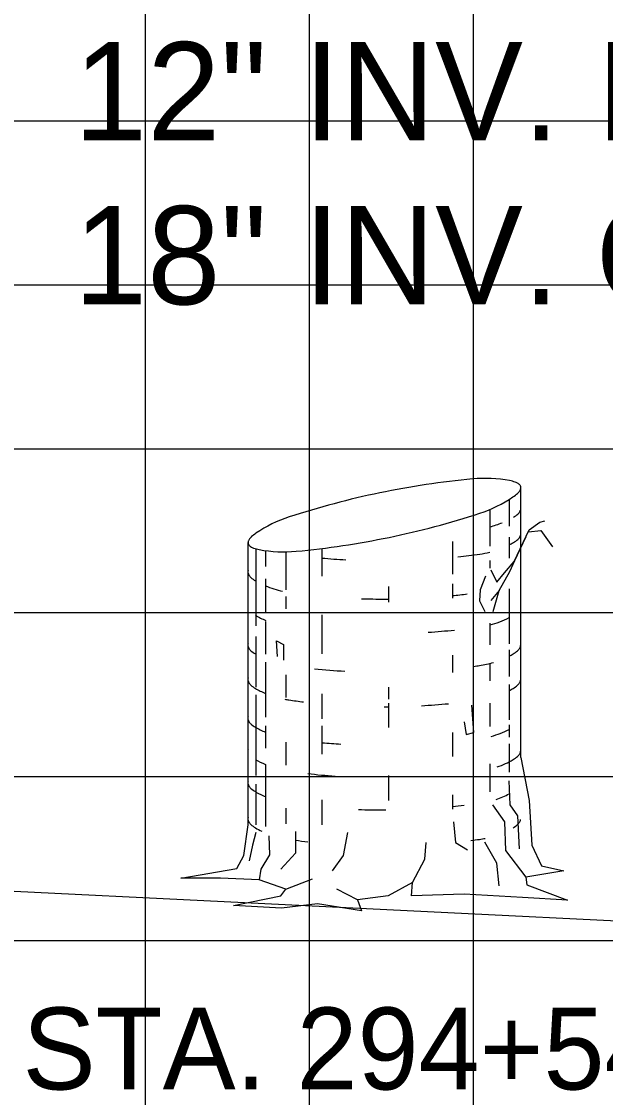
# Model space of a CAD drawing. Extents: x 859352 to 859522, y 366268 to 366378.
# Drawn here: x 859467.37 to 859470.94, y 366286.28 to 366292.84 of the extents above; entities that cross this region are included whole.
import ezdxf

# ---------------------------------------------------------------- set-up
doc = ezdxf.new("R2010")
doc.units = 0
for name, color, linetype in [('D_Drainage_Text', 7, 'Continuous'), ('D_Text_Monospaced', 7, 'Continuous'), ('MAJOR', 7, 'Continuous'), ('MINOR', 7, 'Continuous'), ('S_Roadway_Centerline', 7, 'Continuous'), ('S_Trees_Conifer_Pay', 7, 'Continuous')]:
    doc.layers.add(name, color=color, linetype=linetype)

msp = doc.modelspace()

# ---------------------------------------------------------------- linework, layer by layer
at = {"layer": 'MAJOR'}
for p, q in [((859470.1294, 366277.2365), (859470.1294, 366297.2365)), ((859365.1294, 366292.2365), (859505.1294, 366292.2365)), ((859365.1294, 366287.2365), (859505.1294, 366287.2365))]:
    msp.add_line(p, q, dxfattribs=at)
at = {"layer": 'MINOR'}
for p, q in [((859468.1294, 366277.2365), (859468.1294, 366297.2365)), ((859469.1294, 366277.2365), (859469.1294, 366297.2365)), ((859365.1294, 366291.2365), (859505.1294, 366291.2365)), ((859365.1294, 366290.2365), (859505.1294, 366290.2365)), ((859365.1294, 366289.2365), (859505.1294, 366289.2365)), ((859365.1294, 366288.2365), (859505.1294, 366288.2365))]:
    msp.add_line(p, q, dxfattribs=at)
at = {"layer": 'S_Roadway_Centerline'}
msp.add_lwpolyline([(859463.9377, 366287.7043), (859477.1652, 366287.052), (859487.7669, 366286.7914)], dxfattribs=at)
at = {"layer": 'S_Trees_Conifer_Pay'}
for p, q in [((859470.4189, 366288.352), (859470.4189, 366289.999)), ((859470.3474, 366289.9268), (859470.3474, 366289.7641)), ((859470.2299, 366289.8658), (859470.2299, 366289.6427)), ((859468.7549, 366287.9419), (859468.7549, 366289.6637)), ((859470.0016, 366289.6696), (859470.0016, 366289.4701)), ((859470.3474, 366289.6965), (859470.3474, 366289.5685)), ((859468.8021, 366289.6263), (859468.8021, 366289.1551)), ((859468.8605, 366289.6151), (859468.8605, 366289.5173)), ((859468.9858, 366289.6072), (859468.9858, 366289.375)), ((859469.2056, 366289.6276), (859469.2056, 366289.4596)), ((859470.2299, 366289.5541), (859470.2299, 366289.5068)), ((859468.8605, 366289.4432), (859468.8605, 366289.2391)), ((859469.6112, 366289.396), (859469.6112, 366289.3008)), ((859470.0016, 366289.4124), (859470.0016, 366289.3238)), ((859468.9858, 366289.3343), (859468.9858, 366289.2601)), ((859470.287, 366289.371), (859470.2358, 366289.3113)), ((859470.3474, 366289.3815), (859470.3474, 366289.0456)), ((859469.2056, 366289.2227), (859469.2056, 366288.9859)), ((859468.8605, 366289.1814), (859468.8605, 366288.9819)), ((859470.2299, 366289.1715), (859470.2299, 366289.0397)), ((859468.8021, 366289.0908), (859468.8021, 366288.7824)), ((859470.3474, 366289.0088), (859470.3474, 366288.8461)), ((859468.8605, 366288.9347), (859468.8605, 366288.5987)), ((859470.0016, 366288.976), (859470.0016, 366288.871)), ((859470.2299, 366288.9288), (859470.2299, 366288.8192)), ((859468.9858, 366288.8566), (859468.9858, 366288.7181)), ((859470.3474, 366288.7988), (859470.3474, 366288.5823)), ((859468.8021, 366288.7352), (859468.8021, 366288.2431)), ((859469.2056, 366288.7411), (859469.2056, 366288.5889)), ((859469.6112, 366288.7824), (859469.6112, 366288.7083)), ((859469.6112, 366288.6834), (859469.6112, 366288.5351)), ((859470.2299, 366288.6834), (859470.2299, 366288.5416)), ((859468.8605, 366288.5456), (859468.8605, 366288.4097)), ((859469.2056, 366288.5456), (859469.2056, 366288.3723)), ((859470.3474, 366288.5515), (859470.3474, 366288.4773)), ((859470.0016, 366288.5042), (859470.0016, 366288.3579)), ((859468.9858, 366288.4465), (859468.9858, 366288.3048)), ((859470.3474, 366288.4366), (859470.3474, 366288.2634)), ((859468.8605, 366288.3107), (859468.8605, 366287.932)), ((859470.2299, 366288.3146), (859470.2299, 366288.142)), ((859469.6112, 366288.2431), (859469.6112, 366288.0902)), ((859468.8021, 366288.1893), (859468.8021, 366287.9419)), ((859469.2056, 366288.0948), (859469.2056, 366287.9419)), ((859470.0016, 366288.1256), (859470.0016, 366288.037)), ((859468.9858, 366288.0429), (859468.9858, 366287.9485)), ((859468.9858, 366287.5488), (859469.1486, 366287.6125)), ((859469.4228, 366287.4845), (859469.2969, 366287.5488))]:
    msp.add_line(p, q, dxfattribs=at)
for points in [[(859470.2358, 366289.497), (859470.2726, 366289.4229), (859470.3198, 366289.4799), (859470.3776, 366289.5482), (859470.4701, 366289.7418), (859470.5344, 366289.789), (859470.5652, 366289.7956)], [(859470.4648, 366289.7299), (859470.5403, 366289.7378), (859470.6125, 366289.6387)], [(859470.2503, 366289.2437), (859470.287, 366289.371), (859470.3507, 366289.4865), (859470.3815, 366289.5541), (859470.4504, 366289.7004)], [(859470.2024, 366289.4596), (859470.1715, 366289.375), (859470.1676, 366289.3074), (859470.1984, 366289.2437)], [(859468.934, 366288.9694), (859468.9281, 366289.0646), (859468.9714, 366289.0416), (859468.9714, 366288.9471)], [(859470.0731, 366288.5705), (859470.0856, 366288.4937), (859470.1328, 366288.5042), (859470.1203, 366288.6709)], [(859470.4189, 366288.352), (859470.4701, 366288.0902), (859470.4865, 366287.8166), (859470.5442, 366287.6912), (859470.6801, 366287.6604), (859470.4497, 366287.623), (859470.4497, 366287.623), (859470.4556, 366287.5758), (859470.703, 366287.4813), (859470.4287, 366287.4977), (859470.0731, 366287.518), (859469.7516, 366287.5075), (859469.7581, 366287.5902), (859469.6098, 366287.5075), (859469.4228, 366287.4845), (859469.4471, 366287.417), (859469.1794, 366287.4603), (859468.9589, 366287.4334), (859468.6663, 366287.4504), (859468.955, 366287.5075), (859468.9858, 366287.5488), (859468.8231, 366287.6066), (859468.5862, 366287.6171), (859468.3454, 366287.6171), (859468.6873, 366287.6748), (859468.7286, 366287.7549), (859468.7549, 366287.9419)], [(859470.3448, 366288.2096), (859470.3507, 366288.0639), (859470.3979, 366287.9957), (859470.4084, 366287.7962)], [(859470.2457, 366288.0639), (859470.3198, 366287.959), (859470.3244, 366287.7857), (859470.4497, 366287.623)], [(859470.0088, 366287.959), (859470.0193, 366287.833), (859470.0934, 366287.7897)], [(859468.8028, 366287.8946), (859468.7818, 366287.8166), (859468.7614, 366287.7221)], [(859468.8808, 366287.8743), (859468.8868, 366287.7588), (859468.8336, 366287.6702), (859468.8231, 366287.6066)], [(859469.0436, 366287.9012), (859469.0436, 366287.7693), (859468.955, 366287.6702)], [(859469.27, 366287.6604), (859469.3375, 366287.7549), (859469.3644, 366287.8946)], [(859469.7581, 366287.5902), (859469.8323, 366287.7319), (859469.8421, 366287.833)], [(859470.287, 366287.5698), (859470.2726, 366287.7076), (859470.1984, 366287.8369)]]:
    msp.add_lwpolyline(points, dxfattribs=at)
for centre, radius, start, end in [((859470.6107, 366284.8962), 5.1788, 95.37941, 101.7194), ((859470.2004, 366289.2541), 0.8016, 79.2194, 95.37941), ((859470.3034, 366289.7953), 0.2506, 71.05013, 79.2194), ((859470.3583, 366289.9551), 0.0817, 56.7194, 71.05013), ((859470.3439, 366290.0245), 0.0817, 312.38868, 326.7194), ((859470.3742, 366289.9793), 0.0527, 46.92298, 56.7194), ((859470.3887, 366289.9949), 0.0314, 34.2194, 46.92298), ((859470.3681, 366290.0086), 0.0527, 326.7194, 336.51582), ((859470.3929, 366289.9977), 0.0264, 23.40735, 34.2194), ((859470.3877, 366290.0001), 0.0314, 336.51582, 349.2194), ((859470.3963, 366289.9992), 0.0226, 11.7194, 23.40735), ((859470.3963, 366289.9992), 0.0226, 0.03145, 11.7194), ((859470.3925, 366289.9992), 0.0264, 349.2194, 0.03145), ((859470.6107, 366284.8962), 5.1788, 101.7194, 108.05939), ((859469.9202, 366290.6049), 0.8016, 288.05939, 304.2194), ((859470.23, 366290.1492), 0.2506, 304.2194, 312.38868), ((859470.3596, 366289.8848), 0.0624, 311.25059, 330), ((859470.3755, 366289.8757), 0.0441, 330, 343.94846), ((859470.3858, 366289.8727), 0.0334, 343.94846, 354.21506), ((859469.2538, 366289.0577), 0.8016, 108.05939, 124.2194), ((859468.5632, 366294.7664), 5.1788, 281.7194, 288.05939), ((859470.088, 366290.3125), 0.5707, 284.43166, 292.41325), ((859470.2872, 366289.9674), 0.1723, 300, 311.25059), ((859468.9439, 366289.5133), 0.2506, 124.2194, 132.38868), ((859470.3858, 366289.7183), 0.0334, 343.94846, 354.21506), ((859468.7814, 366289.6634), 0.0264, 169.2194, 180.03145), ((859468.7776, 366289.6634), 0.0226, 180.03145, 191.7194), ((859468.7863, 366289.6625), 0.0314, 156.51582, 169.2194), ((859468.7776, 366289.6634), 0.0226, 191.7194, 203.40735), ((859468.7811, 366289.6649), 0.0264, 203.40735, 214.2194), ((859468.8058, 366289.654), 0.0527, 146.7194, 156.51582), ((859468.7852, 366289.6677), 0.0314, 214.2194, 226.92298), ((859468.8301, 366289.638), 0.0817, 132.38868, 146.7194), ((859468.5632, 366294.7664), 5.1788, 275.37941, 281.7194), ((859470.088, 366290.1581), 0.5707, 297.0237, 300), ((859470.2872, 366289.813), 0.1723, 300, 311.25059), ((859470.3596, 366289.7304), 0.0624, 311.25059, 330), ((859470.3755, 366289.7213), 0.0441, 330, 343.94846), ((859468.7998, 366289.6833), 0.0527, 226.92298, 236.7194), ((859468.8157, 366289.7075), 0.0817, 236.7194, 251.05013), ((859468.8705, 366289.8672), 0.2506, 251.05013, 259.2194), ((859468.9736, 366290.4085), 0.8016, 259.2194, 275.37941), ((859469.5871, 366293.6756), 4.1237, 276.23804, 278.1032), ((859470.088, 366290.1581), 0.5707, 278.1032, 284.36665), ((859469.5871, 366293.6756), 4.1237, 264.6955, 266.73309), ((859468.787, 366289.4854), 0.0334, 163.94846, 180), ((859468.787, 366289.4854), 0.0334, 180, 196.05154), ((859468.7974, 366289.4884), 0.0441, 196.05154, 210), ((859468.8132, 366289.4975), 0.0624, 210, 228.74941), ((859468.8856, 366289.5801), 0.1723, 228.74941, 240), ((859469.0849, 366289.9252), 0.5707, 240, 240.33672), ((859469.0849, 366289.9252), 0.5707, 246.85973, 257.98457), ((859469.5857, 366293.4427), 4.1237, 268.07512, 270), ((859469.5857, 366293.4427), 4.1237, 270, 270.35814), ((859469.5857, 366293.4427), 4.1237, 275.78493, 277.05584), ((859470.3856, 366289.2743), 0.0334, 343.94846, 354.21506), ((859469.0862, 366289.7141), 0.5707, 240, 247.05866), ((859470.0878, 366289.7141), 0.5707, 284.44928, 297.04285), ((859469.587, 366293.2317), 4.1237, 273.70524, 275.95043), ((859468.787, 366289.0386), 0.0334, 163.94846, 180), ((859468.787, 366289.0386), 0.0334, 180, 196.05154), ((859468.7974, 366289.0416), 0.0441, 196.05154, 210), ((859468.8132, 366289.0507), 0.0624, 210, 228.74941), ((859468.8856, 366289.1333), 0.1723, 228.74941, 240), ((859470.2857, 366289.1333), 0.1723, 300, 311.25059), ((859470.3582, 366289.0507), 0.0624, 311.25059, 330), ((859470.374, 366289.0416), 0.0441, 330, 343.94846), ((859470.3843, 366289.0386), 0.0334, 343.94846, 354.21506), ((859469.0849, 366289.4784), 0.5707, 240, 240.33672), ((859470.0865, 366289.4784), 0.5707, 278.1032, 286.92962), ((859470.0865, 366289.4784), 0.5707, 297.18959, 300), ((859469.5857, 366292.9959), 4.1237, 264.08098, 266.66759), ((859469.5857, 366292.9959), 4.1237, 277.61247, 278.1032), ((859468.787, 366288.8286), 0.0334, 163.94846, 180), ((859468.787, 366288.8286), 0.0334, 180, 196.05154), ((859468.7974, 366288.8316), 0.0441, 196.05154, 210), ((859468.8132, 366288.8407), 0.0624, 210, 228.74941), ((859468.8856, 366288.9233), 0.1723, 228.74941, 240), ((859470.2857, 366288.9233), 0.1723, 300, 311.25059), ((859470.3582, 366288.8407), 0.0624, 311.25059, 330), ((859470.374, 366288.8316), 0.0441, 330, 343.94846), ((859470.3843, 366288.8286), 0.0334, 343.94846, 354.21506), ((859469.0849, 366289.2684), 0.5707, 240, 246.85973), ((859470.0865, 366289.2684), 0.5707, 297.18959, 300), ((859469.0849, 366289.2684), 0.5707, 259.27072, 261.8968), ((859469.5857, 366292.7859), 4.1237, 261.8968, 263.14738), ((859469.5857, 366292.7859), 4.1237, 270, 270.35814), ((859469.5857, 366292.7859), 4.1237, 273.14934, 275.45691), ((859468.787, 366288.5918), 0.0334, 163.94846, 180), ((859468.787, 366288.5918), 0.0334, 180, 196.05154), ((859468.7974, 366288.5948), 0.0441, 196.05154, 210), ((859468.8132, 366288.6039), 0.0624, 210, 228.74941), ((859468.8856, 366288.6865), 0.1723, 228.74941, 240), ((859469.0849, 366289.0316), 0.5707, 240, 246.85973), ((859470.0865, 366289.0316), 0.5707, 285.39827, 297.18959), ((859468.787, 366288.3942), 0.0334, 163.94846, 180), ((859469.5857, 366292.5491), 4.1237, 264.71603, 266.31934), ((859469.0741, 366288.84), 0.5707, 241.23686, 248.02677), ((859470.0865, 366288.8339), 0.5707, 289.29072, 300), ((859470.2857, 366288.4889), 0.1723, 300, 311.25059), ((859470.3582, 366288.4063), 0.0624, 311.25059, 330), ((859470.374, 366288.3971), 0.0441, 330, 343.94846), ((859470.3843, 366288.3942), 0.0334, 343.94846, 354.21506), ((859468.787, 366288.1986), 0.0334, 163.94846, 180), ((859469.5857, 366292.3515), 4.1237, 263.49906, 265.83975), ((859468.787, 366288.1986), 0.0334, 180, 196.05154), ((859468.7974, 366288.2015), 0.0441, 196.05154, 210), ((859468.8132, 366288.2107), 0.0624, 210, 228.74941), ((859468.8856, 366288.2933), 0.1723, 228.74941, 240), ((859469.0849, 366288.6383), 0.5707, 240, 246.85973), ((859470.0865, 366288.6383), 0.5707, 288.50673, 297.27208), ((859469.5857, 366292.1559), 4.1237, 267.81166, 270), ((859469.5857, 366292.1559), 4.1237, 270, 270.13279), ((859469.5857, 366292.1559), 4.1237, 275.78493, 276.78961), ((859468.787, 366287.9782), 0.0334, 163.94846, 180), ((859468.787, 366287.9782), 0.0334, 180, 196.05154), ((859468.7974, 366287.9812), 0.0441, 196.05154, 210), ((859468.8132, 366287.9904), 0.0624, 210, 228.74941), ((859468.8856, 366288.073), 0.1723, 228.74941, 240), ((859470.2857, 366288.073), 0.1723, 300, 311.25059), ((859470.3582, 366287.9904), 0.0624, 311.25059, 330), ((859470.374, 366287.9812), 0.0441, 330, 343.94846), ((859470.3843, 366287.9782), 0.0334, 343.94846, 354.21506), ((859469.0849, 366288.418), 0.5707, 240, 244.53138), ((859469.5857, 366291.9356), 4.1237, 262.44379, 263.51202), ((859469.5857, 366291.9356), 4.1237, 277.36842, 278.1032), ((859470.0865, 366288.418), 0.5707, 278.1032, 281.63703)]:
    msp.add_arc(centre, radius, start, end, dxfattribs=at)

# ---------------------------------------------------------------- texts
at = {"layer": 'D_Drainage_Text'}
for s, p in [('12" INV. IN = 244.99\' (AHEAD)', (859467.6938, 366292.1171)), ('18" INV. OUT = 244.49\' (LEFT)', (859467.6938, 366291.1171))]:
    msp.add_text(s, height=0.6, dxfattribs=at).set_placement(p)
at = {"layer": 'D_Text_Monospaced'}
msp.add_text('STA. 294+54.10', height=0.49998, dxfattribs=at).set_placement((859467.3795, 366286.327))

doc.saveas('drawing.dxf')
